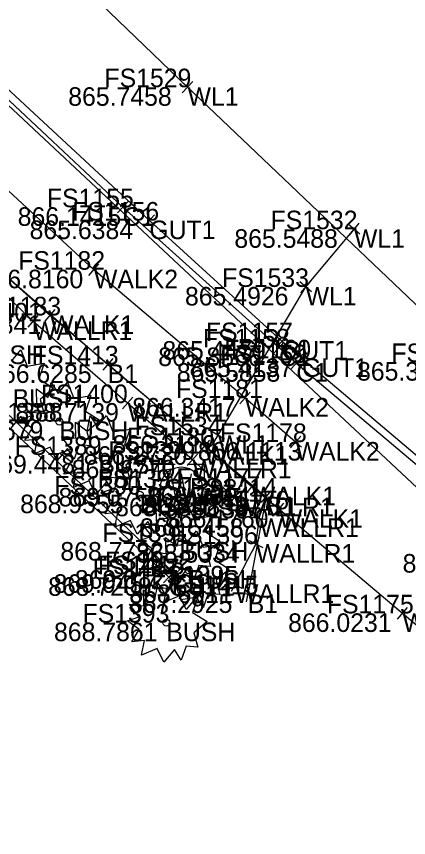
# Model space of a CAD drawing. Extents: x 1469677 to 1493262, y 375219 to 389293.
# Drawn here: x 1479742.1 to 1479767.4, y 379739.8 to 379792.9 of the extents above; entities that cross this region are included whole.
import ezdxf

# ---------------------------------------------------------------- set-up
doc = ezdxf.new("R2010")
doc.units = 0
for name, color, linetype in [('DR_X_Cells', 7, 'Continuous'), ('DR_X_Drive_Pipe', 7, 'Continuous'), ('DV_X_Lot_Line', 7, 'Continuous'), ('DV_X_Text', 7, 'Continuous'), ('GK_Visualization', 7, 'Continuous'), ('PNTELEV', 7, 'Continuous'), ('PNTNO', 7, 'Continuous'), ('RD_P_Text', 7, 'Continuous'), ('RW_P_Const_Limits', 7, 'Continuous'), ('RW_P_Esmt_SW', 7, 'Continuous'), ('SV_X_Mon_Cells_Found', 7, 'Continuous'), ('text', 7, 'Continuous')]:
    doc.layers.add(name, color=color, linetype=linetype)

msp = doc.modelspace()

# ---------------------------------------------------------------- linework, layer by layer
at = {"layer": 'DR_X_Cells'}
msp.add_lwpolyline([(1479756.217, 379756.165), (1479757.574, 379758.774), (1479757.809, 379760.44), (1479756.184, 379761.773), (1479753.461, 379764.221), (1479749.272, 379767.89), (1479743.159, 379773.17), (1479734.585, 379781.475), (1479724.018, 379791.188), (1479717.004, 379797.909), (1479704.341, 379809.227)], dxfattribs=at)
at = {"layer": 'DR_X_Drive_Pipe'}
for points in [[(1479473.217, 380054.881), (1479498.741, 380029.974), (1479514.505, 380014.087), (1479533.448, 379996.736), (1479556.003, 379974.32), (1479574.861, 379956.271), (1479584.403, 379947.432), (1479599.597, 379932.82), (1479630.106, 379903.783), (1479644.769, 379889.723), (1479654.209, 379882.356), (1479664.266, 379872.629), (1479692.509, 379845.847), (1479712.672, 379826.686), (1479730.739, 379809.851), (1479753.15, 379788.309), (1479771.842, 379770.542), (1479781.678, 379761.101)], [(1479763.916, 379779.128), (1479760.787, 379775.399), (1479755.114, 379765.812)]]:
    msp.add_lwpolyline(points, dxfattribs=at)
at = {"layer": 'DV_X_Lot_Line'}
for points in [[(1479760.141, 379765.373), (1479756.862, 379768.221), (1479747.096, 379776.511), (1479736.047, 379786.698), (1479722.324, 379799.575), (1479705.728, 379814.895), (1479685.769, 379833.709)], [(1479782.769, 379741.06), (1479767.055, 379754.294), (1479759.061, 379761.026), (1479757.309, 379762.481), (1479754.256, 379765.105), (1479744.261, 379773.561), (1479732.859, 379783.688), (1479719.35, 379796.385), (1479703.027, 379811.462), (1479682.443, 379830.686)]]:
    msp.add_lwpolyline(points, dxfattribs=at)
at = {"layer": 'PNTELEV'}
for p, q in [((1479752.79, 379788.656), (1479753.51, 379787.963)), ((1479753.496, 379788.67), (1479752.804, 379787.949)), ((1479753.15, 379788.309), (1479753.15, 379788.309)), ((1479748.598, 379780.89), (1479749.328, 379780.206)), ((1479749.305, 379780.913), (1479748.621, 379780.184)), ((1479748.963, 379780.548), (1479748.963, 379780.548)), ((1479750.314, 379780.03), (1479751.046, 379779.35)), ((1479751.02, 379780.057), (1479750.34, 379779.324)), ((1479750.68, 379779.69), (1479750.68, 379779.69)), ((1479764.299, 379778.806), (1479763.533, 379779.449)), ((1479764.237, 379779.511), (1479763.595, 379778.745)), ((1479763.916, 379779.128), (1479763.916, 379779.128)), ((1479747.477, 379776.187), (1479746.715, 379776.834)), ((1479746.772, 379776.129), (1479747.42, 379776.892)), ((1479747.096, 379776.511), (1479747.096, 379776.511)), ((1479761.17, 379775.077), (1479760.404, 379775.72)), ((1479761.108, 379775.782), (1479760.466, 379775.016)), ((1479760.787, 379775.399), (1479760.787, 379775.399)), ((1479744.643, 379773.238), (1479743.879, 379773.884)), ((1479743.938, 379773.179), (1479744.584, 379773.943)), ((1479743.537, 379772.843), (1479742.781, 379773.496)), ((1479742.832, 379772.791), (1479743.486, 379773.548)), ((1479744.261, 379773.561), (1479744.261, 379773.561)), ((1479743.159, 379773.17), (1479743.159, 379773.17)), ((1479758.883, 379772.23), (1479759.623, 379771.557)), ((1479759.589, 379772.263), (1479758.917, 379771.524)), ((1479758.693, 379771.819), (1479759.437, 379771.151)), ((1479759.399, 379771.857), (1479758.731, 379771.113)), ((1479759.253, 379771.893), (1479759.253, 379771.893)), ((1479759.065, 379771.485), (1479759.065, 379771.485)), ((1479760.88, 379771.16), (1479760.23, 379770.4)), ((1479747.613, 379770.72), (1479748.367, 379770.064)), ((1479748.318, 379770.769), (1479747.662, 379770.015)), ((1479759.814, 379770.808), (1479760.556, 379770.138)), ((1479760.52, 379770.844), (1479759.85, 379770.102)), ((1479760.175, 379771.105), (1479760.935, 379770.455)), ((1479760.555, 379770.78), (1479760.555, 379770.78)), ((1479747.99, 379770.392), (1479747.99, 379770.392)), ((1479760.185, 379770.473), (1479760.185, 379770.473)), ((1479757.239, 379767.893), (1479756.485, 379768.549)), ((1479756.534, 379767.844), (1479757.19, 379768.598)), ((1479749.648, 379767.56), (1479748.896, 379768.219)), ((1479748.943, 379767.514), (1479749.601, 379768.266)), ((1479756.862, 379768.221), (1479756.862, 379768.221)), ((1479749.272, 379767.89), (1479749.272, 379767.89)), ((1479755.544, 379765.558), (1479754.684, 379766.067)), ((1479755.369, 379766.243), (1479754.859, 379765.382)), ((1479755.114, 379765.812), (1479755.114, 379765.812)), ((1479754.635, 379764.779), (1479753.877, 379765.431)), ((1479753.93, 379764.726), (1479754.582, 379765.484)), ((1479760.518, 379765.045), (1479759.764, 379765.701)), ((1479759.813, 379764.995), (1479760.469, 379765.75)), ((1479760.141, 379765.373), (1479760.141, 379765.373)), ((1479754.256, 379765.105), (1479754.256, 379765.105)), ((1479753.833, 379763.886), (1479753.089, 379764.555)), ((1479753.127, 379763.849), (1479753.795, 379764.592)), ((1479753.461, 379764.221), (1479753.461, 379764.221)), ((1479757.694, 379762.161), (1479756.924, 379762.8)), ((1479756.99, 379762.096), (1479757.628, 379762.865)), ((1479756.571, 379761.456), (1479755.797, 379762.09)), ((1479755.867, 379761.387), (1479756.501, 379762.16)), ((1479757.309, 379762.481), (1479757.309, 379762.481)), ((1479757.841, 379762.157), (1479758.609, 379761.516)), ((1479758.546, 379762.22), (1479757.904, 379761.453)), ((1479756.184, 379761.773), (1479756.184, 379761.773)), ((1479758.225, 379761.837), (1479758.225, 379761.837)), ((1479759.443, 379760.704), (1479758.679, 379761.348)), ((1479758.739, 379760.644), (1479759.383, 379761.409)), ((1479759.061, 379761.026), (1479759.061, 379761.026)), ((1479757.314, 379760.51), (1479758.304, 379760.37)), ((1479757.739, 379759.945), (1479757.879, 379760.935)), ((1479757.809, 379760.44), (1479757.809, 379760.44)), ((1479757.13, 379759.005), (1479758.018, 379758.543)), ((1479757.343, 379758.331), (1479757.805, 379759.218)), ((1479757.574, 379758.774), (1479757.574, 379758.774)), ((1479752.298, 379756.287), (1479751.568, 379756.97)), ((1479751.592, 379756.263), (1479752.274, 379756.994)), ((1479752.702, 379756.475), (1479751.98, 379757.166)), ((1479751.996, 379756.459), (1479752.686, 379757.182)), ((1479752.341, 379756.82), (1479752.341, 379756.82)), ((1479751.933, 379756.629), (1479751.933, 379756.629)), ((1479755.773, 379756.395), (1479756.661, 379755.934)), ((1479755.986, 379755.721), (1479756.448, 379756.608)), ((1479756.217, 379756.165), (1479756.217, 379756.165)), ((1479757.131, 379756.014), (1479756.947, 379755.032)), ((1479757.53, 379755.431), (1479756.548, 379755.615)), ((1479757.039, 379755.523), (1479757.039, 379755.523)), ((1479766.733, 379753.911), (1479767.377, 379754.676)), ((1479767.437, 379753.972), (1479766.673, 379754.616)), ((1479767.055, 379754.294), (1479767.055, 379754.294))]:
    msp.add_line(p, q, dxfattribs=at)
at = {"layer": 'PNTNO'}
msp.add_line((1479752.745, 379762.409), (1479752.745, 379762.409), dxfattribs=at)
for points in [[(1479752.345, 379763.909), (1479751.245, 379763.909), (1479751.245, 379762.809)], [(1479754.245, 379762.809), (1479754.245, 379763.909), (1479753.145, 379763.909)], [(1479752.078, 379763.309), (1479752.412, 379761.509), (1479752.745, 379763.309), (1479753.078, 379761.509), (1479753.412, 379763.309)], [(1479751.245, 379762.009), (1479751.245, 379760.909), (1479752.345, 379760.909)], [(1479753.145, 379760.909), (1479754.245, 379760.909), (1479754.245, 379762.009)]]:
    msp.add_lwpolyline(points, dxfattribs=at)
msp.add_circle((1479752.745, 379762.409), 1.35, dxfattribs=at)
at = {"layer": 'RD_P_Text'}
for points in [[(1479752.341, 379756.82), (1479734.895, 379773.493), (1479717.229, 379789.662), (1479699.298, 379806.402), (1479688.16, 379794.934), (1479685.526, 379793.897), (1479682.733, 379795.157), (1479681.263, 379797.549), (1479682.493, 379800.746), (1479693.462, 379811.911), (1479675.554, 379828.75), (1479655.832, 379847.057), (1479640.191, 379861.809), (1479628.558, 379849), (1479624.614, 379847.664), (1479622.46, 379848.585), (1479618.996, 379850.857), (1479611.825, 379854.437), (1479601.319, 379856.892), (1479590.521, 379858.039)], [(1479751.933, 379756.629), (1479734.447, 379772.976), (1479716.701, 379789.463), (1479699.4, 379805.742), (1479688.561, 379794.786), (1479685.717, 379793.294), (1479682.291, 379794.8), (1479680.73, 379797.254), (1479682.169, 379801.19), (1479692.652, 379811.907), (1479675.183, 379828.391), (1479655.51, 379846.682), (1479640.151, 379860.926), (1479629.134, 379848.869), (1479624.571, 379847.215), (1479622.228, 379847.911), (1479618.757, 379850.398), (1479611.519, 379853.97), (1479601.347, 379856.369), (1479590.364, 379857.442)], [(1479695.384, 379831.416), (1479709.512, 379818.131), (1479724.003, 379804.728), (1479730.662, 379798.272), (1479750.68, 379779.69), (1479759.253, 379771.893), (1479760.555, 379770.78), (1479775.03, 379758.526)], [(1479695.135, 379830.979), (1479709.331, 379817.708), (1479723.729, 379804.193), (1479729.719, 379798.6), (1479748.963, 379780.548), (1479759.065, 379771.485), (1479760.185, 379770.473), (1479774.837, 379758.13)]]:
    msp.add_lwpolyline(points, dxfattribs=at)
at = {"layer": 'RW_P_Const_Limits'}
for points in [[(1479741.752, 379770.599), (1479742.357, 379771.334), (1479742.772, 379770.28), (1479743.864, 379770.46), (1479743.525, 379769.449), (1479744.47, 379768.854), (1479743.614, 379768.119), (1479743.864, 379767.205), (1479743.11, 379767.274), (1479742.785, 379766.36), (1479742.357, 379767.052), (1479741.679, 379766.235)], [(1479744.773, 379768.51), (1479745.378, 379769.245), (1479745.793, 379768.191), (1479746.885, 379768.371), (1479746.546, 379767.36), (1479747.491, 379766.765), (1479746.635, 379766.03), (1479746.885, 379765.116), (1479746.131, 379765.185), (1479745.806, 379764.271), (1479745.378, 379764.963), (1479744.7, 379764.146), (1479744.271, 379765.033), (1479743.251, 379764.603), (1479743.443, 379765.545), (1479742.631, 379765.461), (1479743.105, 379766.251), (1479742.336, 379766.82), (1479743.075, 379767.083), (1479742.468, 379767.886), (1479743.4, 379767.776), (1479743.37, 379768.815), (1479744.123, 379768.246), (1479744.33, 379769.231), (1479744.773, 379768.51)], [(1479747.296, 379766.346), (1479747.901, 379767.081), (1479748.316, 379766.027), (1479749.408, 379766.207), (1479749.069, 379765.196), (1479750.014, 379764.601), (1479749.158, 379763.866), (1479749.408, 379762.952), (1479748.654, 379763.021), (1479748.329, 379762.107), (1479747.901, 379762.799), (1479747.223, 379761.982), (1479746.794, 379762.869), (1479745.774, 379762.439), (1479745.966, 379763.381), (1479745.154, 379763.297), (1479745.628, 379764.087), (1479744.859, 379764.656), (1479745.598, 379764.919), (1479744.991, 379765.722), (1479745.923, 379765.612), (1479745.893, 379766.651), (1479746.646, 379766.082), (1479746.853, 379767.067), (1479747.296, 379766.346)], [(1479749.972, 379763.781), (1479750.577, 379764.516), (1479750.992, 379763.462), (1479752.084, 379763.642), (1479751.745, 379762.631), (1479752.69, 379762.036), (1479751.834, 379761.301), (1479752.084, 379760.387), (1479751.33, 379760.456), (1479751.005, 379759.542), (1479750.577, 379760.234), (1479749.899, 379759.417), (1479749.47, 379760.304), (1479748.45, 379759.874), (1479748.642, 379760.816), (1479747.83, 379760.732), (1479748.304, 379761.522), (1479747.535, 379762.091), (1479748.274, 379762.354), (1479747.667, 379763.157), (1479748.599, 379763.047), (1479748.569, 379764.086), (1479749.322, 379763.517), (1479749.529, 379764.502), (1479749.972, 379763.781)], [(1479752.529, 379760.716), (1479753.134, 379761.451), (1479753.549, 379760.398), (1479754.641, 379760.578), (1479754.302, 379759.566), (1479755.247, 379758.971), (1479754.391, 379758.236), (1479754.641, 379757.323), (1479753.887, 379757.391), (1479753.562, 379756.478), (1479753.134, 379757.169), (1479752.456, 379756.353), (1479752.027, 379757.239), (1479751.007, 379756.809), (1479751.199, 379757.751), (1479750.387, 379757.668), (1479750.861, 379758.458), (1479750.092, 379759.026), (1479750.831, 379759.289), (1479750.224, 379760.093), (1479751.156, 379759.983), (1479751.126, 379761.021), (1479751.879, 379760.453), (1479752.086, 379761.438), (1479752.529, 379760.716)], [(1479753.133, 379758.898), (1479753.738, 379759.633), (1479754.153, 379758.58), (1479755.245, 379758.76), (1479754.906, 379757.748), (1479755.851, 379757.153), (1479754.995, 379756.418), (1479755.245, 379755.505), (1479754.491, 379755.573), (1479754.166, 379754.66), (1479753.738, 379755.352), (1479753.06, 379754.535), (1479752.631, 379755.422), (1479751.611, 379754.992), (1479751.803, 379755.933), (1479750.991, 379755.85), (1479751.465, 379756.64), (1479750.696, 379757.208), (1479751.435, 379757.472), (1479750.828, 379758.275), (1479751.76, 379758.165), (1479751.73, 379759.203), (1479752.483, 379758.635), (1479752.69, 379759.62), (1479753.133, 379758.898)], [(1479751.694, 379755.506), (1479752.299, 379756.241), (1479752.714, 379755.188), (1479753.806, 379755.368), (1479753.467, 379754.356), (1479754.412, 379753.761), (1479753.556, 379753.026), (1479753.806, 379752.113), (1479753.052, 379752.181), (1479752.727, 379751.268), (1479752.299, 379751.959), (1479751.621, 379751.143), (1479751.192, 379752.029), (1479750.172, 379751.599), (1479750.364, 379752.541), (1479749.552, 379752.458), (1479750.026, 379753.248), (1479749.257, 379753.816), (1479749.996, 379754.079), (1479749.389, 379754.883), (1479750.321, 379754.773), (1479750.291, 379755.811), (1479751.044, 379755.243), (1479751.251, 379756.228), (1479751.694, 379755.506)]]:
    msp.add_lwpolyline(points, dxfattribs=at)
for centre in [(1479744.857, 379766.7), (1479747.38, 379764.536), (1479750.056, 379761.971), (1479752.613, 379758.906), (1479753.217, 379757.089), (1479751.778, 379753.697)]:
    msp.add_circle(centre, 0.23, dxfattribs=at)
at = {"layer": 'SV_X_Mon_Cells_Found'}
msp.add_lwpolyline([(1477164.629, 382297.849), (1479615.888, 379904.59), (1480413.414, 379159.216)], dxfattribs=at)
at = {"layer": 'text'}
msp.add_lwpolyline([(1479700.791, 379810.474), (1479703.421, 379811.158), (1479704.398, 379810.048), (1479708.429, 379806.714), (1479717.526, 379798.095), (1479729.107, 379786.809), (1479738.375, 379778.754), (1479747.99, 379770.392), (1479758.225, 379761.837), (1479757.039, 379755.523)], dxfattribs=at)

# ---------------------------------------------------------------- texts
at = {"layer": 'DV_X_Text'}
for s, p in [('865.7458', (1479745.431, 379787.109)), ('866.1415', (1479742.162, 379779.348)), ('865.6384', (1479742.932, 379778.49)), ('865.5488', (1479756.178, 379777.928)), ('866.8160', (1479739.708, 379775.311)), ('865.4926', (1479752.983, 379774.199)), ('866.7841', (1479736.984, 379772.361)), ('865.4479', (1479751.524, 379770.693)), ('865.8566', (1479751.251, 379770.285)), ('865.4137', (1479753.281, 379769.58)), ('866.6285', (1479740.252, 379769.192)), ('865.5858', (1479752.456, 379769.273)), ('865.3828', (1479764.113, 379769.342)), ('866.3417', (1479749.569, 379767.021)), ('868.7139', (1479742.016, 379766.69)), ('869.2679', (1479737.129, 379765.5)), ('866.3119', (1479748.294, 379764.612)), ('866.1113', (1479753.822, 379764.173)), ('866.2730', (1479746.433, 379763.905)), ('869.4481', (1479740.075, 379763.336)), ('868.6770', (1479745.657, 379763.021)), ('869.0750', (1479744.808, 379761.209)), ('866.1614', (1479750.507, 379761.281)), ('868.9555', (1479742.319, 379760.771)), ('868.5842', (1479748.465, 379760.573)), ('866.0833', (1479750.355, 379760.637)), ('866.1760', (1479751.692, 379759.826)), ('868.5458', (1479750.071, 379759.24)), ('868.7732', (1479744.923, 379757.706)), ('868.5334', (1479749.826, 379757.574)), ('865.3697', (1479767.061, 379756.93)), ('869.0457', (1479744.48, 379755.62)), ('869.0127', (1479745.858, 379755.888)), ('868.7208', (1479744.129, 379755.429)), ('868.6911', (1479749.384, 379754.965)), ('867.2925', (1479749.358, 379754.323)), ('866.0231', (1479759.655, 379753.094)), ('868.7861', (1479744.511, 379752.496))]:
    msp.add_text(s, height=1.2, dxfattribs=at).set_placement(p)
at = {"layer": 'GK_Visualization'}
for s, p in [('WL1', (1479753.15, 379787.109)), ('C1', (1479748.963, 379779.348)), ('GUT1', (1479750.68, 379778.49)), ('WL1', (1479763.916, 379777.928)), ('WALK2', (1479747.096, 379775.311)), ('WL1', (1479760.787, 379774.199)), ('WALK1', (1479744.261, 379772.361)), ('WALLR1', (1479743.159, 379771.97)), ('GUT1', (1479759.253, 379770.693)), ('BUSH', (1479739.403, 379770.414)), ('C1', (1479759.065, 379770.285)), ('GUT1', (1479760.555, 379769.58)), ('B1', (1479747.99, 379769.192)), ('C1', (1479760.185, 379769.273)), ('BUSH', (1479741.837, 379767.589)), ('WALK2', (1479756.862, 379767.021)), ('WALLR1', (1479749.272, 379766.69)), ('BUSH', (1479744.858, 379765.5)), ('WL1', (1479755.114, 379764.612)), ('WALK2', (1479760.141, 379764.173)), ('WALK1', (1479754.256, 379763.905)), ('BUSH', (1479747.381, 379763.336)), ('WALLR1', (1479753.461, 379763.021)), ('WME', (1479752.745, 379761.209)), ('WALK1', (1479757.309, 379761.281)), ('BUSH', (1479750.057, 379760.771)), ('WALLR1', (1479756.184, 379760.573)), ('B1', (1479758.225, 379760.637)), ('WALK1', (1479759.061, 379759.826)), ('WALLR1', (1479757.809, 379759.24)), ('BUSH', (1479752.614, 379757.706)), ('WALLR1', (1479757.574, 379757.574)), ('C1', (1479752.341, 379755.62)), ('BUSH', (1479753.218, 379755.888)), ('GUT1', (1479751.933, 379755.429)), ('WALLR1', (1479756.217, 379754.965)), ('B1', (1479757.039, 379754.323)), ('WALK1', (1479767.055, 379753.094)), ('BUSH', (1479751.779, 379752.496))]:
    msp.add_text(s, height=1.2, dxfattribs=at).set_placement(p)
at = {"layer": 'RW_P_Esmt_SW'}
for s, p in [('FS1529', (1479747.775, 379788.309)), ('FS1155', (1479744.051, 379780.548)), ('FS1156', (1479745.693, 379779.69)), ('FS1532', (1479758.522, 379779.128)), ('FS1182', (1479742.194, 379776.511)), ('FS1533', (1479755.383, 379775.399)), ('FS1401', (1479738.103, 379773.17)), ('FS1183', (1479739.349, 379773.561)), ('FS1158', (1479754.144, 379771.485)), ('FS1157', (1479754.341, 379771.893)), ('FS1159', (1479755.264, 379770.473)), ('FS1160', (1479755.52, 379770.78)), ('FS1530', (1479766.334, 379770.542)), ('FS1413', (1479743.069, 379770.392)), ('FS1400', (1479743.66, 379767.89)), ('FS1181', (1479752.401, 379768.221)), ('FS1388', (1479739.445, 379766.7)), ('FS1534', (1479749.72, 379765.812)), ('FS1178', (1479755.239, 379765.373)), ('FS1180', (1479749.24, 379765.105)), ('FS1389', (1479741.968, 379764.536)), ('FS1399', (1479748.029, 379764.221)), ('FS1177', (1479752.416, 379762.481)), ('FS1390', (1479744.53, 379761.971)), ('FS1394', (1479747.332, 379762.409)), ('FS1398', (1479750.752, 379761.773)), ('FS1414', (1479753.313, 379761.837)), ('FS1176', (1479754.093, 379761.026)), ('FS1397', (1479752.386, 379760.44)), ('FS1391', (1479747.643, 379758.906)), ('FS1396', (1479752.076, 379758.774)), ('FS1417', (1479747.012, 379756.629)), ('FS1416', (1479747.344, 379756.82)), ('FS1392', (1479747.805, 379757.088)), ('FS1395', (1479750.794, 379756.165)), ('FS1415', (1479752.118, 379755.523)), ('FS1175', (1479762.162, 379754.294)), ('FS1393', (1479746.356, 379753.696))]:
    msp.add_text(s, height=1.2, dxfattribs=at).set_placement(p)

doc.saveas('drawing.dxf')
